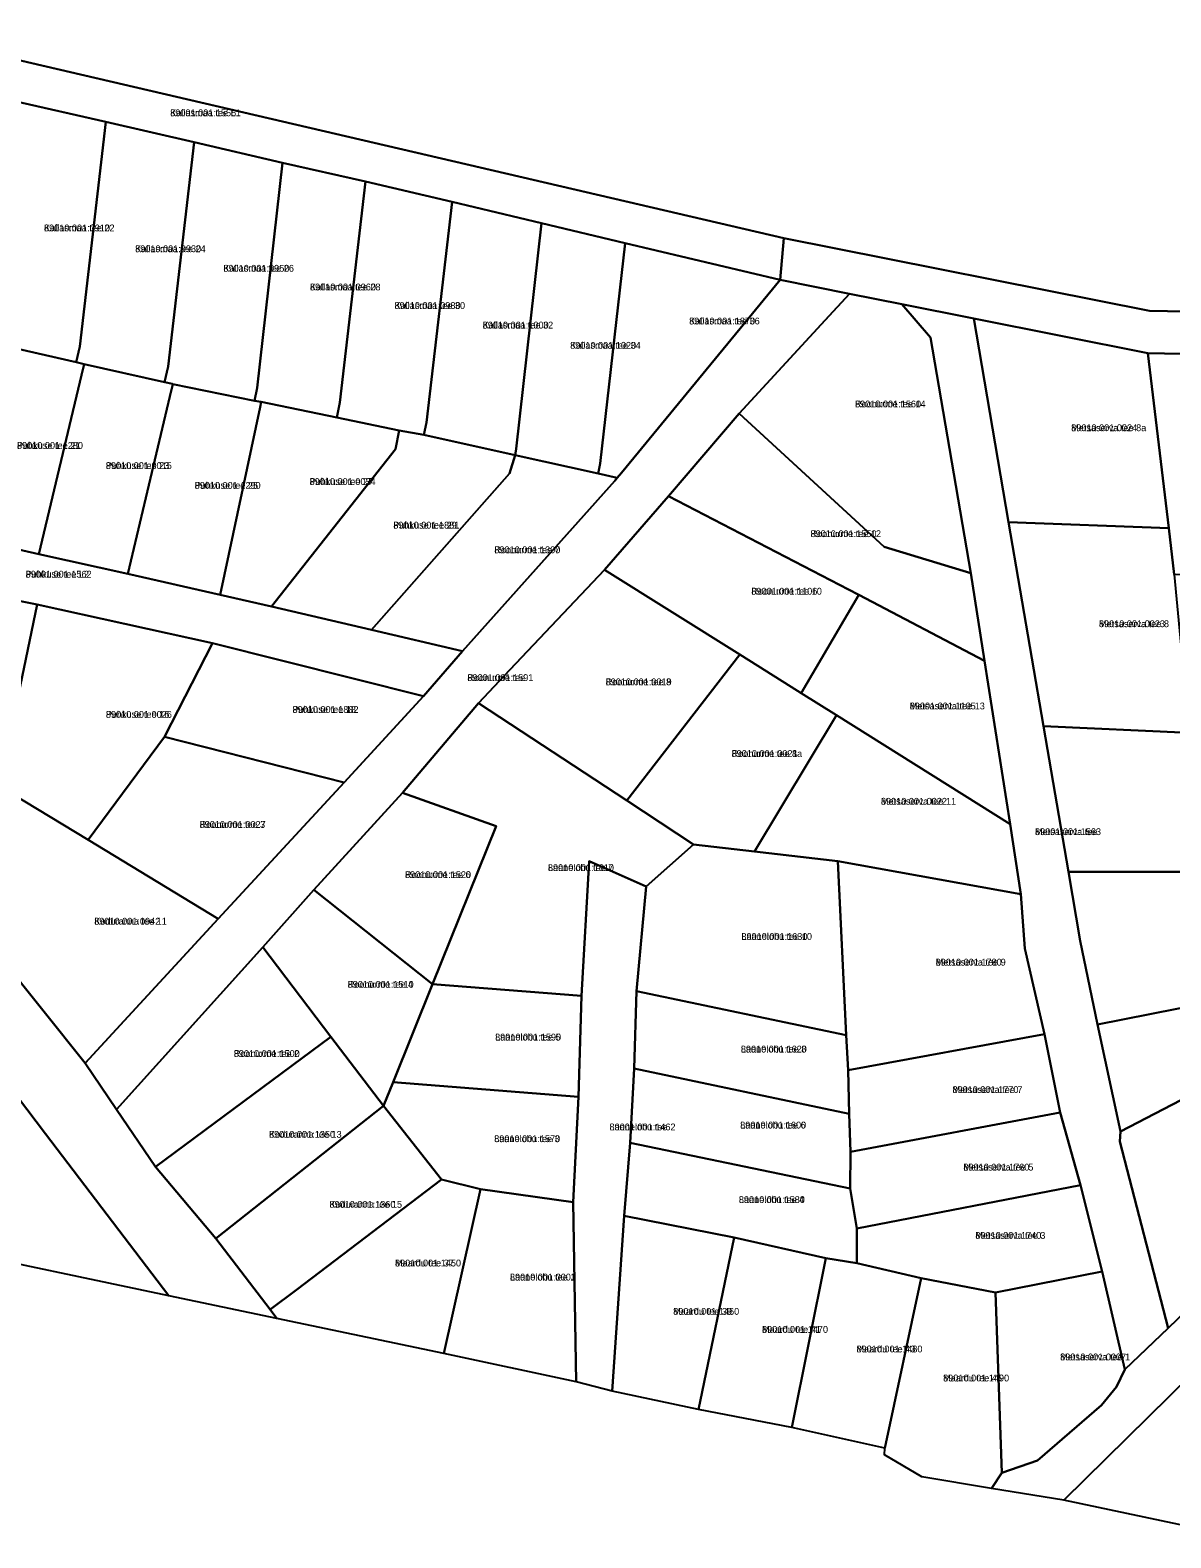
# Model space of a CAD drawing. Extents: x 526849 to 562296, y 6591741 to 6618546.
# Drawn here: x 554059.6 to 554310.3, y 6594037.4 to 6594368.5 of the extents above; entities that cross this region are included whole.
import ezdxf

# ---------------------------------------------------------------- set-up
doc = ezdxf.new("R2010")
doc.units = 0
for name, color, linetype in [('L_AADRESS', 7, 'Continuous'), ('PIIR', 7, 'Continuous'), ('TUNNUS', 7, 'Continuous')]:
    doc.layers.add(name, color=color, linetype=linetype)

msp = doc.modelspace()

# ---------------------------------------------------------------- linework, layer by layer
at = {"layer": 'PIIR'}
for points in [[(554049.07, 6594588.34), (554187.3, 6594577.01), (554142.16, 6594463.53), (554286.81, 6594430.65), (554294.86, 6594427.18), (554295.56, 6594417.13), (554326.06, 6594416.22), (554335.74, 6594428.53), (554338.1, 6594444.44), (554360.54, 6594442.08), (554393.31, 6594337.56), (554366.29, 6594332.23), (554326.99, 6594325.2), (554329.5, 6594306.39), (554305.59, 6594306.85), (554225.23, 6594322.81), (554036.66, 6594366.61)], [(554036.66, 6594366.61), (554225.23, 6594322.81), (554224.46, 6594313.63), (554190.41, 6594321.68), (554171.99, 6594326.09), (554152.41, 6594330.78), (554133.3, 6594335.21), (554115.07, 6594339.37), (554095.65, 6594343.86), (554076.31, 6594348.33), (554056.29, 6594352.88)], [(554330.91, 6594297.04), (554305.24, 6594297.53), (554266.97, 6594305.17), (554251.16, 6594308.3), (554239.7, 6594310.59), (554224.46, 6594313.63), (554225.23, 6594322.81), (554305.59, 6594306.85), (554329.5, 6594306.39)], [(554053.1, 6594164.88), (554071.71, 6594141.64), (554078.63, 6594131.47), (554087.21, 6594118.85), (554100.41, 6594103.09), (554112.38, 6594087.49), (554113.86, 6594085.56), (554090.15, 6594090.55), (554063.05, 6594126.12), (554042.66, 6594152.88)], [(554323.89, 6594082.19), (554286.8, 6594045.65), (554270.86, 6594048.2), (554273.13, 6594051.68), (554280.98, 6594054.38), (554295.07, 6594066.54), (554298.38, 6594070.52), (554300.15, 6594074.38), (554309.72, 6594083.45), (554325.75, 6594098.85)]]:
    msp.add_lwpolyline(points, dxfattribs=at)
for points in [[(554049.07, 6594300.27), (554050.09, 6594304.89), (554056.29, 6594352.88), (554076.31, 6594348.33), (554070.55, 6594298.97), (554069.79, 6594295.53), (554052.01, 6594299.6)], [(554069.79, 6594295.53), (554070.55, 6594298.97), (554076.31, 6594348.33), (554095.65, 6594343.86), (554089.94, 6594294.6), (554089.16, 6594291.14), (554071.51, 6594295.13)], [(554089.16, 6594291.14), (554089.94, 6594294.6), (554095.65, 6594343.86), (554115.07, 6594339.37), (554109.51, 6594289.92), (554108.97, 6594287.09), (554091.01, 6594290.76), (554090.93, 6594290.78)], [(554109.51, 6594289.92), (554115.07, 6594339.37), (554133.3, 6594335.21), (554127.66, 6594286.73), (554127.02, 6594283.42), (554110.44, 6594286.87), (554108.97, 6594287.09)], [(554127.66, 6594286.73), (554133.3, 6594335.21), (554152.41, 6594330.78), (554146.71, 6594282.28), (554146.14, 6594279.58), (554140.71, 6594280.57), (554127.02, 6594283.42)], [(554146.71, 6594282.28), (554152.41, 6594330.78), (554171.99, 6594326.09), (554166.46, 6594276.5), (554166.2, 6594275.13), (554146.14, 6594279.58)], [(554166.46, 6594276.5), (554171.99, 6594326.09), (554190.41, 6594321.68), (554184.9, 6594273.31), (554184.44, 6594271.08), (554166.2, 6594275.13)], [(554188.63, 6594270.14), (554184.44, 6594271.08), (554184.9, 6594273.31), (554190.41, 6594321.68), (554224.46, 6594313.63), (554189.55, 6594271.26)], [(554199.91, 6594266.12), (554185.83, 6594249.94), (554165.07, 6594227.97), (554158.14, 6594220.69), (554141.46, 6594200.97), (554121.97, 6594179.69), (554110.74, 6594167.11), (554083.33, 6594136.67), (554078.63, 6594131.47), (554071.71, 6594141.64), (554100.98, 6594173.29), (554128.64, 6594203.25), (554146.08, 6594222.18), (554154.67, 6594232.1), (554188.1, 6594269.54), (554188.63, 6594270.14), (554189.55, 6594271.26), (554224.46, 6594313.63), (554239.7, 6594310.59), (554234.31, 6594304.76), (554215.45, 6594284.32)], [(554247.33, 6594254.98), (554215.45, 6594284.32), (554234.31, 6594304.76), (554239.7, 6594310.59), (554251.16, 6594308.3), (554257.49, 6594300.96), (554266.34, 6594249.22)], [(554277.29, 6594178.74), (554274.98, 6594194.14), (554269.37, 6594229.98), (554266.34, 6594249.22), (554257.49, 6594300.96), (554251.16, 6594308.3), (554266.97, 6594305.17), (554274.63, 6594260.46), (554282.31, 6594215.6), (554287.78, 6594183.63), (554290.38, 6594168.45), (554294.14, 6594150.13), (554299.25, 6594126.65), (554299.05, 6594124.39), (554309.72, 6594083.45), (554300.15, 6594074.38), (554295.19, 6594095.84), (554290.46, 6594114.83), (554285.96, 6594130.78), (554282.49, 6594147.99), (554278.17, 6594166.78)], [(554274.63, 6594260.46), (554266.97, 6594305.17), (554305.24, 6594297.53), (554309.82, 6594259.09)], [(554051.46, 6594297.31), (554052.01, 6594299.6), (554069.79, 6594295.53), (554071.51, 6594295.13), (554070.92, 6594292.68), (554061.54, 6594253.42), (554041.99, 6594257.89)], [(554305.24, 6594297.53), (554330.91, 6594297.04), (554336.45, 6594247.79), (554311.04, 6594248.95), (554309.82, 6594259.09)], [(554061.54, 6594253.42), (554070.92, 6594292.68), (554071.51, 6594295.13), (554089.16, 6594291.14), (554090.93, 6594290.78), (554091.01, 6594290.76), (554090.37, 6594288.06), (554081.13, 6594249.06)], [(554090.37, 6594288.06), (554091.01, 6594290.76), (554108.97, 6594287.09), (554110.44, 6594286.87), (554110.18, 6594285.67), (554101.4, 6594244.44), (554081.13, 6594249.06)], [(554110.44, 6594286.87), (554127.02, 6594283.42), (554140.71, 6594280.57), (554139.9, 6594276.44), (554112.68, 6594241.92), (554101.4, 6594244.44), (554110.18, 6594285.67)], [(554215.45, 6594284.32), (554247.33, 6594254.98), (554266.34, 6594249.22), (554269.37, 6594229.98), (554241.76, 6594244.48), (554239.45, 6594245.67), (554199.91, 6594266.12)], [(554165, 6594271.11), (554134.65, 6594236.77), (554112.68, 6594241.92), (554139.9, 6594276.44), (554140.71, 6594280.57), (554146.14, 6594279.58), (554166.2, 6594275.13)], [(554101.4, 6594244.44), (554112.68, 6594241.92), (554134.65, 6594236.77), (554154.67, 6594232.1), (554146.08, 6594222.18), (554099.71, 6594233.82), (554061.19, 6594242.35), (554042.57, 6594246.09), (553987.58, 6594258.02), (553970.54, 6594274.32), (553983.71, 6594271.26), (554003.35, 6594266.66), (554022.42, 6594262.29), (554041.99, 6594257.89), (554061.54, 6594253.42), (554081.13, 6594249.06)], [(554188.1, 6594269.54), (554154.67, 6594232.1), (554134.65, 6594236.77), (554165, 6594271.11), (554166.2, 6594275.13), (554184.44, 6594271.08), (554188.63, 6594270.14)], [(554185.83, 6594249.94), (554199.91, 6594266.12), (554239.45, 6594245.67), (554241.76, 6594244.48), (554229.08, 6594222.9), (554226.86, 6594224.28), (554215.56, 6594231.38)], [(554282.31, 6594215.6), (554274.63, 6594260.46), (554309.82, 6594259.09), (554311.04, 6594248.95), (554314.34, 6594214.15)], [(554185.83, 6594249.94), (554215.56, 6594231.38), (554190.72, 6594199.28), (554158.14, 6594220.69), (554165.07, 6594227.97)], [(554022.97, 6594205.25), (554042.57, 6594246.09), (554061.19, 6594242.35), (554052.86, 6594202.44), (554036.73, 6594186.34)], [(554229.08, 6594222.9), (554241.76, 6594244.48), (554269.37, 6594229.98), (554274.98, 6594194.14), (554236.81, 6594218.03)], [(554061.19, 6594242.35), (554099.71, 6594233.82), (554089.18, 6594213.29), (554072.36, 6594190.63), (554052.86, 6594202.44)], [(554089.18, 6594213.29), (554099.71, 6594233.82), (554146.08, 6594222.18), (554128.64, 6594203.25)], [(554215.56, 6594231.38), (554226.86, 6594224.28), (554229.08, 6594222.9), (554236.81, 6594218.03), (554218.8, 6594188.1), (554205.38, 6594189.65), (554190.72, 6594199.28)], [(554194.97, 6594180.44), (554182.5, 6594186), (554180.81, 6594156.4), (554148.08, 6594158.95), (554162.07, 6594193.66), (554141.46, 6594200.97), (554158.14, 6594220.69), (554190.72, 6594199.28), (554205.38, 6594189.65)], [(554236.81, 6594218.03), (554274.98, 6594194.14), (554277.29, 6594178.74), (554237.15, 6594185.99), (554218.8, 6594188.1)], [(554282.31, 6594215.6), (554314.34, 6594214.15), (554315.58, 6594201.04), (554336.2, 6594200.59), (554338.01, 6594183.63), (554287.78, 6594183.63)], [(554089.18, 6594213.29), (554128.64, 6594203.25), (554100.98, 6594173.29), (554072.36, 6594190.63)], [(554053.1, 6594164.88), (554036.73, 6594186.34), (554052.86, 6594202.44), (554072.36, 6594190.63), (554100.98, 6594173.29), (554071.71, 6594141.64)], [(554148.08, 6594158.95), (554121.97, 6594179.69), (554141.46, 6594200.97), (554162.07, 6594193.66)], [(554238.92, 6594147.74), (554192.9, 6594157.41), (554194.97, 6594180.44), (554205.38, 6594189.65), (554218.8, 6594188.1), (554237.15, 6594185.99)], [(554190.19, 6594108.13), (554187.54, 6594069.56), (554179.61, 6594071.61), (554178.93, 6594111.11), (554180.14, 6594134.23), (554180.81, 6594156.4), (554182.5, 6594186), (554194.97, 6594180.44), (554192.9, 6594157.41), (554192.33, 6594140.45), (554191.45, 6594124.11)], [(554237.15, 6594185.99), (554277.29, 6594178.74), (554278.17, 6594166.78), (554282.49, 6594147.99), (554239.42, 6594140.11), (554238.92, 6594147.74)], [(554287.78, 6594183.63), (554338.01, 6594183.63), (554339.05, 6594173.82), (554340.2, 6594163.84), (554340.87, 6594159.31), (554294.14, 6594150.13), (554290.38, 6594168.45)], [(554125.72, 6594147.39), (554110.74, 6594167.11), (554121.97, 6594179.69), (554148.08, 6594158.95), (554139.42, 6594137.44), (554137.32, 6594132.25)], [(554125.72, 6594147.39), (554087.21, 6594118.85), (554078.63, 6594131.47), (554083.33, 6594136.67), (554110.74, 6594167.11)], [(554148.08, 6594158.95), (554180.81, 6594156.4), (554180.14, 6594134.23), (554139.42, 6594137.44)], [(554318.11, 6594136.46), (554299.25, 6594126.65), (554294.14, 6594150.13), (554340.87, 6594159.31), (554341.75, 6594148.51)], [(554239.58, 6594130.52), (554192.33, 6594140.45), (554192.9, 6594157.41), (554238.92, 6594147.74), (554239.42, 6594140.11)], [(554024.01, 6594127.88), (554042.66, 6594152.88), (554063.05, 6594126.12), (554090.15, 6594090.55), (554038.7, 6594101.39), (554034.49, 6594102.2), (554009.89, 6594108.34), (554015.54, 6594115.73)], [(554239.42, 6594140.11), (554282.49, 6594147.99), (554285.96, 6594130.78), (554239.91, 6594122.15), (554239.58, 6594130.52)], [(554137.32, 6594132.25), (554100.41, 6594103.09), (554087.21, 6594118.85), (554125.72, 6594147.39)], [(554239.8, 6594114.09), (554191.45, 6594124.11), (554192.33, 6594140.45), (554239.58, 6594130.52), (554239.91, 6594122.15)], [(554139.42, 6594137.44), (554180.14, 6594134.23), (554178.93, 6594111.11), (554158.57, 6594113.97), (554150.02, 6594116.1), (554137.32, 6594132.25)], [(554318.11, 6594136.46), (554325.75, 6594098.85), (554309.72, 6594083.45), (554299.05, 6594124.39), (554299.25, 6594126.65)], [(554150.02, 6594116.1), (554118.14, 6594091.87), (554112.38, 6594087.49), (554100.41, 6594103.09), (554137.32, 6594132.25)], [(554239.91, 6594122.15), (554285.96, 6594130.78), (554290.46, 6594114.83), (554241.26, 6594105.3), (554239.8, 6594114.09)], [(554214.34, 6594103.35), (554190.19, 6594108.13), (554191.45, 6594124.11), (554239.8, 6594114.09), (554241.26, 6594105.3), (554241.28, 6594097.72), (554234.45, 6594098.78)], [(554158.57, 6594113.97), (554150.52, 6594077.85), (554113.86, 6594085.56), (554112.38, 6594087.49), (554118.14, 6594091.87), (554150.02, 6594116.1)], [(554241.26, 6594105.3), (554290.46, 6594114.83), (554295.19, 6594095.84), (554271.77, 6594091.28), (554255.39, 6594094.4), (554241.28, 6594097.72)], [(554158.57, 6594113.97), (554178.93, 6594111.11), (554179.61, 6594071.61), (554150.52, 6594077.85)], [(554214.34, 6594103.35), (554206.48, 6594065.55), (554187.54, 6594069.56), (554190.19, 6594108.13)], [(554234.45, 6594098.78), (554227.04, 6594061.58), (554206.48, 6594065.55), (554214.34, 6594103.35)], [(554255.39, 6594094.4), (554247.41, 6594057.1), (554227.04, 6594061.58), (554234.45, 6594098.78), (554241.28, 6594097.72)], [(554300.15, 6594074.38), (554298.38, 6594070.52), (554295.07, 6594066.54), (554280.98, 6594054.38), (554273.13, 6594051.68), (554271.77, 6594091.28), (554295.19, 6594095.84)], [(554271.77, 6594091.28), (554273.13, 6594051.68), (554270.86, 6594048.2), (554255.55, 6594050.77), (554247.36, 6594055.59), (554247.41, 6594057.1), (554255.39, 6594094.4)], [(554325.88, 6594037.38), (554286.8, 6594045.65), (554323.89, 6594082.19), (554336.58, 6594079.51)]]:
    msp.add_lwpolyline(points, close=True, dxfattribs=at)

# ---------------------------------------------------------------- texts
at = {"layer": 'L_AADRESS'}
for s, p in [('Kallasmaa tee L1', (554090.42, 6594349.57)), ('Kallasmaa tee 22', (554062.69, 6594324.29)), ('Kallasmaa tee 24', (554082.72, 6594319.72)), ('Kallasmaa tee 26', (554102.11, 6594315.43)), ('Kallasmaa tee 28', (554121.13, 6594311.32)), ('Kallasmaa tee 30', (554139.71, 6594307.25)), ('Kallasmaa tee 32', (554159.07, 6594302.95)), ('Kallasmaa tee 36', (554204.45, 6594303.85)), ('Kallasmaa tee 34', (554178.3, 6594298.51)), ('Roonurme tee 14', (554240.9, 6594285.63)), ('Metsaserva tee 8a', (554288.39, 6594280.41)), ('Puhkuse tee 21', (554056.75, 6594276.52)), ('Puhkuse tee 23', (554076.27, 6594272.1)), ('Puhkuse tee 27', (554121.05, 6594268.6)), ('Puhkuse tee 25', (554095.79, 6594267.75)), ('Puhkuse tee 29', (554139.44, 6594259.02)), ('Roonurme tee 12', (554231.11, 6594257.15)), ('Roonurme tee 7', (554161.64, 6594253.61)), ('Puhkuse tee L2', (554058.65, 6594248.25)), ('Roonurme tee 10', (554218.11, 6594244.51)), ('Metsaserva tee 8', (554294.49, 6594237.37)), ('Roonurme tee', (554155.71, 6594225.54)), ('Roonurme tee 8', (554186.1, 6594224.61)), ('Metsaserva tee 13', (554252.91, 6594219.31)), ('Puhkuse tee 16', (554076.29, 6594217.46)), ('Puhkuse tee 18', (554117.3, 6594218.54)), ('Roonurme tee 8a', (554213.77, 6594208.87)), ('Metsaserva tee 11', (554246.59, 6594198.38)), ('Roonurme tee 3', (554096.89, 6594193.29)), ('Metsaserva tee', (554280.44, 6594191.71)), ('Laanelohu tee 7', (554173.42, 6594183.81)), ('Roonurme tee 6', (554142.02, 6594182.27)), ('Koduranna tee 11', (554073.73, 6594172.04)), ('Laanelohu tee 10', (554215.93, 6594168.69)), ('Metsaserva tee 9', (554258.62, 6594163.05)), ('Roonurme tee 4', (554129.41, 6594158.18)), ('Laanelohu tee 5', (554161.81, 6594146.59)), ('Roonurme tee 2', (554104.39, 6594142.98)), ('Laanelohu tee 8', (554215.81, 6594143.96)), ('Metsaserva tee 7', (554262.3, 6594135.07)), ('Laanelohu tee', (554186.95, 6594126.86)), ('Laanelohu tee 6', (554215.66, 6594127.27)), ('Koduranna tee 13', (554112.14, 6594125.24)), ('Laanelohu tee 3', (554161.61, 6594124.28)), ('Metsaserva tee 5', (554264.7, 6594118.04)), ('Koduranna tee 15', (554125.41, 6594109.87)), ('Laanelohu tee 4', (554215.37, 6594110.91)), ('Metsaserva tee 3', (554267.33, 6594103.05)), ('Maardu tee 37', (554139.82, 6594096.98)), ('Laanelohu tee 1', (554165.07, 6594093.89)), ('Maardu tee 39', (554200.94, 6594086.36)), ('Maardu tee 41', (554220.46, 6594082.4)), ('Maardu tee 43', (554241.21, 6594078.1)), ('Metsaserva tee 1', (554285.96, 6594076.36)), ('Maardu tee 45', (554260.25, 6594071.73))]:
    msp.add_text(s, height=1.5, dxfattribs=at).set_placement(p)
at = {"layer": 'TUNNUS'}
for s, p in [('89001:001:1555', (554090.42, 6594349.57)), ('89010:001:0910', (554062.69, 6594324.29)), ('89010:001:0930', (554082.72, 6594319.72)), ('89010:001:0950', (554102.11, 6594315.43)), ('89010:001:0960', (554121.13, 6594311.32)), ('89010:001:0980', (554139.71, 6594307.25)), ('89010:001:1000', (554159.07, 6594302.95)), ('89010:001:1870', (554204.45, 6594303.85)), ('89010:001:1020', (554178.3, 6594298.51)), ('89010:001:1560', (554240.9, 6594285.63)), ('89010:001:0024', (554288.39, 6594280.41)), ('89010:001:1280', (554056.75, 6594276.52)), ('89010:001:0015', (554076.27, 6594272.1)), ('89010:001:0034', (554121.05, 6594268.6)), ('89010:001:1290', (554095.79, 6594267.75)), ('89010:001:1881', (554139.44, 6594259.02)), ('89010:001:1550', (554231.11, 6594257.15)), ('89010:001:1300', (554161.64, 6594253.61)), ('89001:001:1562', (554058.65, 6594248.25)), ('89001:001:1106', (554218.11, 6594244.51)), ('89010:001:0023', (554294.49, 6594237.37)), ('89001:001:1591', (554155.71, 6594225.54)), ('89010:001:0019', (554186.1, 6594224.61)), ('89001:001:1105', (554252.91, 6594219.31)), ('89010:001:0026', (554076.29, 6594217.46)), ('89010:001:1882', (554117.3, 6594218.54)), ('89010:001:0021', (554213.77, 6594208.87)), ('89010:001:0022', (554246.59, 6594198.38)), ('89010:001:0027', (554096.89, 6594193.29)), ('89001:001:1563', (554280.44, 6594191.71)), ('89010:001:1610', (554173.42, 6594183.81)), ('89010:001:1520', (554142.02, 6594182.27)), ('89010:001:0942', (554073.73, 6594172.04)), ('89010:001:1630', (554215.93, 6594168.69)), ('89010:001:1780', (554258.62, 6594163.05)), ('89010:001:1510', (554129.41, 6594158.18)), ('89010:001:1590', (554161.81, 6594146.59)), ('89010:001:1500', (554104.39, 6594142.98)), ('89010:001:1620', (554215.81, 6594143.96)), ('89010:001:1770', (554262.3, 6594135.07)), ('89001:001:1462', (554186.95, 6594126.86)), ('89010:001:1600', (554215.66, 6594127.27)), ('89010:001:1350', (554112.14, 6594125.24)), ('89010:001:1570', (554161.61, 6594124.28)), ('89010:001:1760', (554264.7, 6594118.04)), ('89010:001:1360', (554125.41, 6594109.87)), ('89010:001:1580', (554215.37, 6594110.91)), ('89010:001:1740', (554267.33, 6594103.05)), ('89010:001:1450', (554139.82, 6594096.98)), ('89010:001:0003', (554165.07, 6594093.89)), ('89010:001:1460', (554200.94, 6594086.36)), ('89010:001:1470', (554220.46, 6594082.4)), ('89010:001:1480', (554241.21, 6594078.1)), ('89010:001:0007', (554285.96, 6594076.36)), ('89010:001:1490', (554260.25, 6594071.73))]:
    msp.add_text(s, height=1.5, dxfattribs=at).set_placement(p)

doc.saveas('drawing.dxf')
